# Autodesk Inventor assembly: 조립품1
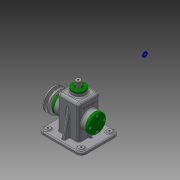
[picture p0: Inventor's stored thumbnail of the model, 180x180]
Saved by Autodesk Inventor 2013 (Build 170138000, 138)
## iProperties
Created: 2016-01
Part Number: 조립품1
Document SubType Name: Assembly
Designer: Administrator
Author: Administrator
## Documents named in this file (19)
- C:\Users\Administrator\Desktop\460127V1009\조립품1.iam
- C:\Users\Administrator\Desktop\460127V1009\부품1.ipt
- C:\Users\Administrator\Desktop\460127V1009\V-벨트풀리.ipt
- C:\Users\Administrator\Desktop\460127V1009\고정핀.ipt
- C:\Users\Administrator\Desktop\460127V1009\뒤커버.ipt
- C:\Users\Administrator\Desktop\460127V1009\링크.ipt
- C:\Users\Administrator\Desktop\460127V1009\멈춤링 6 x 5.ipt
- C:\Users\Administrator\Desktop\460127V1009\멈춤링 15 x 1.ipt
- C:\Users\Administrator\Desktop\460127V1009\베어링 15 x 35 x 11.ipt
- C:\Users\Administrator\Desktop\460127V1009\볼트 M3 x 8.ipt
- C:\Users\Administrator\Desktop\460127V1009\볼트 M4 x 10.ipt
- C:\Users\Administrator\Desktop\460127V1009\볼트 M6 x 12.ipt
- C:\Users\Administrator\Desktop\460127V1009\상부부시.ipt
- C:\Users\Administrator\Desktop\460127V1009\슬라이드바.ipt
- C:\Users\Administrator\Desktop\460127V1009\앞커버.ipt
- C:\Users\Administrator\Desktop\460127V1009\오일실 15 25 7.ipt
- C:\Users\Administrator\Desktop\460127V1009\와셔.ipt
- C:\Users\Administrator\Desktop\460127V1009\키 5 x 5 x 14.ipt
- C:\Users\Administrator\Desktop\460127V1009\편심축.ipt
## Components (19 placed, 5 different names)
1. V-벨트풀리:1 — 각도:2
2. 고정핀:1
3. ISO 4018 M6 x 12:5
4. ISO 4762 M3 x 8:1
5. ISO 4762 M3 x 8:2
6. ISO 4762 M3 x 8:3
7. ISO 4762 M3 x 8:4
8. ISO 4762 M4 x 10:1
9. ISO 4762 M4 x 10:2
10. ISO 4762 M4 x 10:3
11. ISO 4762 M4 x 10:4
12. ISO 4762 M4 x 10:5
13. ISO 4762 M4 x 10:6
14. ISO 4762 M4 x 10:7
15. ISO 4762 M4 x 10:8
16. ISO 4762 M4 x 10:9
17. ISO 4762 M4 x 10:10
18. ISO 4762 M4 x 10:11
19. ISO 4762 M4 x 10:12
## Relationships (1: Angle 1)
- 각도:2 [Angle]: V-벨트풀리:1
